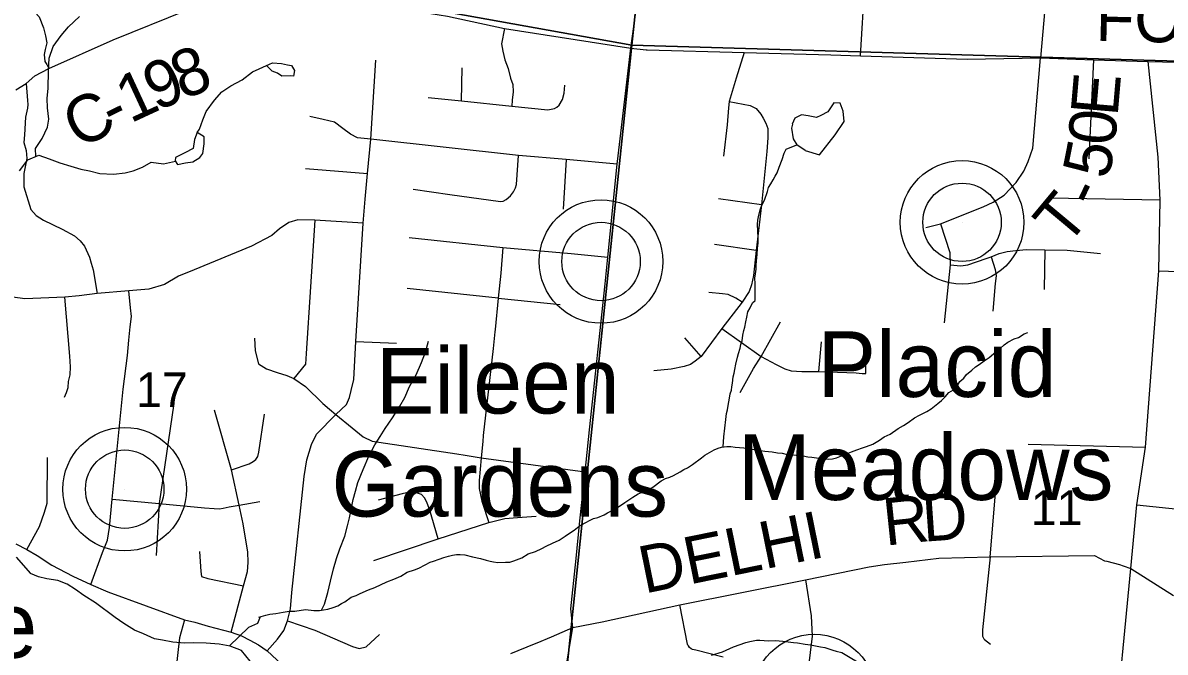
# Model space of a CAD drawing. Extents: x 0 to 34, y 0 to 22.
# Drawn here: x 6.917 to 8.292, y 15.497 to 16.255 of the extents above; entities that cross this region are included whole.
import ezdxf

# ---------------------------------------------------------------- set-up
doc = ezdxf.new("R2010")
doc.units = 0
for name, color, linetype in [('GM_X_Corporation', 7, 'Continuous'), ('GM_X_County_Road', 7, 'Continuous'), ('GM_X_County_Road_Text', 7, 'Continuous'), ('GM_X_Minor_Lake', 7, 'Continuous'), ('GM_X_Minor_River', 7, 'Continuous'), ('GM_X_Section_Text', 7, 'Continuous'), ('GM_X_Township_Road', 7, 'Continuous'), ('GM_X_Township_Road_Text', 7, 'Continuous'), ('GM_X_Unincorporated', 7, 'Continuous'), ('GM_X_Unincorporated_Location', 7, 'Continuous'), ('GM_X_Unincorporated_Text', 7, 'Continuous')]:
    doc.layers.add(name, color=color, linetype=linetype)

msp = doc.modelspace()

# ---------------------------------------------------------------- linework, layer by layer
at = {"layer": 'GM_X_Corporation'}
for points in [[(7.7575, 17.2431), (7.6501, 16.2281), (6.6267, 16.412), (6.7271, 17.3517)], [(7.7575, 17.2431), (8.7485, 17.1931), (8.6363, 16.199), (7.6501, 16.2281)], [(7.6501, 16.2281), (7.5438, 15.2065), (6.5194, 15.3963), (6.6267, 16.412)], [(8.6363, 16.199), (8.5356, 15.1763), (7.5438, 15.2065), (7.6501, 16.2281)]]:
    msp.add_lwpolyline(points, close=True, dxfattribs=at)
at = {"layer": 'GM_X_County_Road'}
for p, q in [((8.1491, 16.294), (8.1419, 16.2128)), ((7.5696, 15.4719), (7.579, 15.5268))]:
    msp.add_line(p, q, dxfattribs=at)
for points in [[(7.5825, 15.6055), (7.5876, 15.6552), (7.5938, 15.7142), (7.5992, 15.7646), (7.6179, 15.9406), (7.6211, 15.9725), (7.6324, 16.0848), (7.6334, 16.0947), (7.6488, 16.2243), (7.6616, 16.3174), (7.6639, 16.369), (7.6701, 16.4334), (7.6877, 16.6246), (7.6932, 16.6628)], [(6.9083, 16.174), (6.921, 16.1818), (6.9314, 16.1911), (6.9481, 16.2), (7.0257, 16.2344), (7.1152, 16.2704), (7.1761, 16.2963), (7.1774, 16.2968), (7.1787, 16.2968), (7.1812, 16.2964), (7.1889, 16.2949), (7.2573, 16.2866), (7.3578, 16.2742), (7.4283, 16.2628), (7.4967, 16.2481), (7.6488, 16.2243), (7.6674, 16.2224), (7.6684, 16.2224)], [(7.6684, 16.2224), (7.7851, 16.2192), (7.8897, 16.2164), (7.9253, 16.2153), (8.0538, 16.2113), (8.1419, 16.2128)], [(8.1419, 16.2128), (8.2056, 16.2102), (8.2716, 16.2083)], [(8.2507, 15.5975), (8.258, 15.6744), (8.2685, 15.744), (8.2845, 15.9563), (8.2862, 16.0414), (8.2836, 16.093), (8.2716, 16.2083)], [(8.2716, 16.2083), (8.427, 16.2047), (8.4709, 16.2033), (8.4984, 16.2029), (8.639, 16.2005)], [(8.2845, 15.9563), (8.4847, 15.9494), (8.6082, 15.9452), (8.7294, 15.9293), (8.7612, 15.9252)], [(8.258, 15.6744), (8.3155, 15.6683), (8.37, 15.6624), (8.4552, 15.6596), (8.5777, 15.6456), (8.693, 15.6342), (8.8525, 15.6133), (8.88, 15.6103), (8.9, 15.6093)], [(6.9083, 15.6272), (6.9219, 15.6204), (6.934, 15.6132), (6.9518, 15.6015), (6.9771, 15.5884), (6.9986, 15.5785), (7.0192, 15.5696), (7.1116, 15.536), (7.1241, 15.5332), (7.1402, 15.5282), (7.1676, 15.5211), (7.1803, 15.5165), (7.1902, 15.5115), (7.2006, 15.5058), (7.2112, 15.4987), (7.2347, 15.4766)], [(7.536, 15.5083), (7.5532, 15.5155), (7.579, 15.5268), (7.6143, 15.5334), (7.7079, 15.5539), (7.8591, 15.5842), (7.9358, 15.5995), (7.9541, 15.6024), (7.98, 15.6051), (8.0195, 15.6103), (8.0814, 15.6119), (8.2071, 15.6132), (8.219, 15.6071), (8.2217, 15.6066), (8.2369, 15.6023), (8.2415, 15.6007)], [(7.5775, 15.5567), (7.5818, 15.5986), (7.5825, 15.6055)], [(8.2129, 15.2407), (8.2301, 15.3849), (8.2507, 15.5975)], [(8.2415, 15.6007), (8.2507, 15.5975), (8.302, 15.5653)], [(7.579, 15.5268), (7.5767, 15.5489), (7.5775, 15.5567)], [(7.7598, 15.4908), (7.7271, 15.4992), (7.723, 15.5001), (7.7213, 15.5011), (7.7196, 15.5025), (7.7182, 15.5044), (7.7175, 15.5055), (7.7171, 15.5067), (7.7079, 15.5539)], [(7.5042, 15.4951), (7.5327, 15.5069), (7.536, 15.5083)]]:
    msp.add_lwpolyline(points, dxfattribs=at)
at = {"layer": 'GM_X_Minor_Lake'}
msp.add_line((7.1006, 16.0928), (7.1003, 16.0886), dxfattribs=at)
for points in [[(7.1933, 16.1959), (7.2137, 16.2049), (7.2175, 16.2067), (7.2281, 16.2057), (7.2357, 16.2043), (7.2402, 16.2034), (7.2438, 16.1976), (7.2429, 16.1908), (7.2395, 16.1909), (7.2285, 16.1908), (7.2236, 16.1944), (7.2169, 16.1968), (7.2132, 16.2007)], [(7.2132, 16.2007), (7.2102, 16.2034)], [(7.8587, 16.1012), (7.8761, 16.096), (7.8949, 16.1199), (7.9055, 16.1359), (7.9043, 16.1485), (7.9008, 16.1581), (7.8932, 16.1586), (7.8861, 16.1478), (7.8776, 16.1434), (7.8723, 16.1409), (7.8621, 16.1427), (7.8541, 16.144), (7.8461, 16.14), (7.8432, 16.1329)], [(7.8433, 16.133), (7.8424, 16.128), (7.8443, 16.115), (7.8487, 16.1081)], [(7.1003, 16.0886), (7.103, 16.0841), (7.1126, 16.0861), (7.1217, 16.0874), (7.1298, 16.0925), (7.1334, 16.0977), (7.1352, 16.109), (7.135, 16.1174), (7.1268, 16.1229), (7.1236, 16.1143), (7.1218, 16.1037), (7.1121, 16.0982), (7.1048, 16.0946)], [(7.8587, 16.1012), (7.8487, 16.1081)], [(7.1048, 16.0946), (7.1006, 16.0928)]]:
    msp.add_lwpolyline(points, dxfattribs=at)
at = {"layer": 'GM_X_Minor_River'}
for points in [[(6.9324, 16.0937), (6.9322, 16.1037), (6.94, 16.1157), (6.9465, 16.1292), (6.9482, 16.139), (6.9467, 16.1527), (6.9462, 16.1637), (6.9473, 16.1762), (6.9478, 16.1967), (6.9486, 16.2123), (6.9535, 16.2262), (6.9629, 16.2397), (6.9719, 16.2501), (6.9852, 16.2627)], [(7.1267, 16.1227), (7.1296, 16.127), (7.1337, 16.1379), (7.1374, 16.1481), (7.1476, 16.1618), (7.1566, 16.1719), (7.1674, 16.1792), (7.1809, 16.1864), (7.1933, 16.1959)], [(7.7986, 15.9203), (7.7984, 15.9411), (7.7982, 15.9472), (7.7987, 15.9525), (7.7996, 15.9582), (7.7997, 15.9631), (7.8002, 15.9677), (7.8008, 15.9757), (7.8014, 15.9829), (7.802, 15.9894), (7.8021, 15.9958), (7.8016, 16.0042), (7.8014, 16.0118), (7.8016, 16.0172), (7.8024, 16.0213), (7.8037, 16.0266), (7.805, 16.0308), (7.8066, 16.0353), (7.8098, 16.0413), (7.8132, 16.0519), (7.8144, 16.0564), (7.8172, 16.0609), (7.82, 16.0658), (7.8224, 16.0703), (7.8248, 16.0744), (7.8273, 16.0812), (7.8309, 16.0902), (7.8334, 16.0978), (7.8358, 16.1027), (7.8487, 16.1081)], [(6.9129, 16.0765), (6.9231, 16.0899), (6.9361, 16.0953), (6.9485, 16.0911), (6.9613, 16.0863), (6.9745, 16.0821), (6.9866, 16.0788), (6.9971, 16.0766), (7.0096, 16.0733), (7.0262, 16.0725), (7.04, 16.0744), (7.0499, 16.0765), (7.061, 16.0811), (7.0714, 16.0869), (7.0864, 16.0852), (7.1005, 16.0882)], [(7.7601, 15.7441), (7.7607, 15.7563), (7.7631, 15.7772), (7.7641, 15.7844), (7.765, 15.7889), (7.7659, 15.7938), (7.7676, 15.8029), (7.7685, 15.8079), (7.7698, 15.8124), (7.7703, 15.8166), (7.7711, 15.8207), (7.7721, 15.8287), (7.773, 15.8329), (7.7739, 15.8374), (7.7752, 15.8438), (7.7773, 15.8522), (7.7786, 15.8567), (7.7803, 15.8631), (7.7812, 15.8673), (7.7828, 15.8718), (7.7837, 15.8787), (7.785, 15.8843), (7.7859, 15.8885), (7.7872, 15.8949), (7.7885, 15.9002), (7.7898, 15.9067), (7.7926, 15.9115), (7.7954, 15.9176), (7.7986, 15.9203)], [(7.2763, 15.5474), (7.2799, 15.5546), (7.2841, 15.5686), (7.2874, 15.5826), (7.2908, 15.5973), (7.2945, 15.6098), (7.2985, 15.6215), (7.3045, 15.6365), (7.3078, 15.649), (7.3103, 15.6588), (7.3146, 15.6808), (7.3175, 15.691), (7.32, 15.7012), (7.3264, 15.717), (7.3336, 15.7328), (7.3407, 15.7467), (7.347, 15.7565), (7.3529, 15.7662), (7.3619, 15.7793), (7.3706, 15.7932), (7.3769, 15.8037), (7.3825, 15.8169), (7.3904, 15.8311), (7.3968, 15.8458), (7.4016, 15.8583), (7.4053, 15.8715)], [(7.8619, 15.7321), (7.8668, 15.7316), (7.8725, 15.7311), (7.8775, 15.7305), (7.8828, 15.7296), (7.8873, 15.7295), (7.8915, 15.7298), (7.8965, 15.7311), (7.9023, 15.7333), (7.9065, 15.7351), (7.9146, 15.7383), (7.9207, 15.7404), (7.9276, 15.7432), (7.9326, 15.7446), (7.9403, 15.7474), (7.948, 15.7522), (7.9538, 15.7562), (7.9608, 15.7594), (7.9708, 15.7664), (7.977, 15.7697), (7.9825, 15.7737), (7.9902, 15.7792), (7.9964, 15.7824), (8.0052, 15.7868), (8.0103, 15.7901), (8.0184, 15.7963), (8.0227, 15.8), (8.027, 15.8044), (8.0317, 15.8096), (8.0371, 15.8129), (8.0426, 15.8189), (8.045, 15.823), (8.0497, 15.827), (8.0529, 15.8315), (8.0591, 15.8367), (8.0638, 15.8407), (8.068, 15.8433), (8.0742, 15.8477), (8.08, 15.8517), (8.0882, 15.8587), (8.0933, 15.8628), (8.0983, 15.8672), (8.1026, 15.8701), (8.1103, 15.8741), (8.1153, 15.8759), (8.1222, 15.8802), (8.1268, 15.882)], [(7.2011, 15.5392), (7.2095, 15.5416), (7.2141, 15.5426), (7.2213, 15.5436), (7.2301, 15.5449), (7.2374, 15.5462), (7.2442, 15.5464), (7.2572, 15.5483), (7.2671, 15.5472), (7.2739, 15.5471), (7.2789, 15.5477), (7.2842, 15.5487), (7.2904, 15.5508), (7.2961, 15.5529), (7.3004, 15.5555), (7.3046, 15.5576), (7.312, 15.5631), (7.3181, 15.5652), (7.3231, 15.5674), (7.3332, 15.5721), (7.3405, 15.5749), (7.3551, 15.5817), (7.3636, 15.5849), (7.372, 15.5885), (7.3797, 15.5932), (7.3882, 15.596), (7.3936, 15.5982), (7.4013, 15.6022), (7.4071, 15.6054), (7.4113, 15.6064), (7.4182, 15.6089), (7.4236, 15.6111), (7.4293, 15.6124), (7.4343, 15.6138), (7.4389, 15.6144), (7.4435, 15.6147), (7.4491, 15.6141), (7.4582, 15.6116), (7.4677, 15.6098), (7.4745, 15.6077), (7.4794, 15.6064), (7.4835, 15.6056), (7.4888, 15.6047), (7.498, 15.6052), (7.5033, 15.6054), (7.5079, 15.6068), (7.5175, 15.6107), (7.5252, 15.6154), (7.5341, 15.6182), (7.5418, 15.6218), (7.5468, 15.6244), (7.5545, 15.628), (7.5626, 15.6319), (7.5699, 15.6367), (7.575, 15.6403), (7.5804, 15.644), (7.5866, 15.6488), (7.5939, 15.6528), (7.5997, 15.656), (7.604, 15.6578), (7.6089, 15.6592), (7.6166, 15.6624), (7.6209, 15.6646), (7.6278, 15.6682), (7.6329, 15.6711), (7.6414, 15.677), (7.6464, 15.6802), (7.6511, 15.6835), (7.6576, 15.6875), (7.6696, 15.6925), (7.6754, 15.6958), (7.6854, 15.7031), (7.6905, 15.7061), (7.6958, 15.7078), (7.7001, 15.7096), (7.7082, 15.7139), (7.7128, 15.7169), (7.7171, 15.719), (7.7229, 15.723), (7.7337, 15.7311), (7.738, 15.7341), (7.7434, 15.7373), (7.7492, 15.7406), (7.7538, 15.7424), (7.758, 15.7438), (7.7645, 15.7447), (7.7691, 15.7446), (7.7744, 15.7437), (7.7797, 15.7436), (7.785, 15.743), (7.7896, 15.7421), (7.7998, 15.7407), (7.81, 15.7389), (7.8191, 15.7383), (7.8255, 15.7369), (7.8309, 15.7364), (7.8369, 15.7351), (7.8411, 15.735), (7.8513, 15.7339), (7.8562, 15.7334), (7.8619, 15.7321)], [(6.9089, 15.6114), (6.926, 15.5915)], [(7.1905, 15.4862), (7.1802, 15.499), (7.1663, 15.5042), (7.1534, 15.5065), (7.1375, 15.5076), (7.1227, 15.508), (7.1117, 15.5079), (7.0973, 15.509), (7.0852, 15.5112), (7.0754, 15.513), (7.0623, 15.519), (7.0514, 15.5234), (7.0383, 15.5314), (7.0279, 15.5388), (7.0044, 15.5565), (6.9902, 15.5652), (6.9805, 15.5723), (6.9701, 15.5786), (6.9592, 15.5831), (6.9456, 15.5853), (6.9357, 15.5875), (6.926, 15.5915)], [(7.2026, 15.5396), (7.1992, 15.5315), (7.1885, 15.5265), (7.1655, 15.5044)], [(7.7459, 15.4931), (7.759, 15.4973), (7.7724, 15.5034), (7.7874, 15.5087), (7.792, 15.5097), (7.8, 15.5114), (7.8042, 15.5113), (7.8145, 15.5106), (7.8228, 15.5108), (7.8316, 15.5102), (7.8448, 15.5086), (7.8494, 15.5081), (7.8588, 15.5067), (7.8649, 15.5058), (7.877, 15.5035), (7.8823, 15.5026), (7.8921, 15.4993)], [(7.8921, 15.4993), (7.8959, 15.4981), (7.9027, 15.4964), (7.915, 15.4892), (7.9195, 15.4864), (7.9233, 15.484), (7.9338, 15.4787), (7.9387, 15.4771), (7.947, 15.4749), (7.9575, 15.4712), (7.9673, 15.4675), (7.9775, 15.4638), (7.9805, 15.463), (7.9854, 15.4621), (7.9884, 15.4616)]]:
    msp.add_lwpolyline(points, dxfattribs=at)
at = {"layer": 'GM_X_Township_Road'}
for p, q in [((7.4449, 16.1609), (7.4459, 16.2006)), ((8.2056, 16.2102), (8.2, 16.0909)), ((7.5711, 16.0902), (7.5672, 16.0304)), ((7.2571, 16.0796), (7.332, 16.0735)), ((7.8061, 16.0358), (7.7542, 16.0428)), ((8.2862, 16.0414), (8.1535, 16.0438)), ((7.4948, 15.9843), (7.4924, 15.9533)), ((7.7995, 15.9807), (7.7497, 15.9879)), ((8.1472, 15.9815), (8.1465, 15.9338)), ((7.4892, 15.9232), (7.3797, 15.935)), ((7.4892, 15.9232), (7.5636, 15.9158)), ((7.8058, 15.853), (7.829, 15.8948)), ((7.3178, 15.8712), (7.3666, 15.8689)), ((7.7336, 15.8531), (7.7137, 15.8754)), ((7.8752, 15.8351), (7.8782, 15.8707)), ((8.1273, 15.7474), (8.2685, 15.744)), ((8.0814, 15.6119), (8.0889, 15.7028))]:
    msp.add_line(p, q, dxfattribs=at)
for points in [[(7.9253, 16.2153), (7.9303, 16.3013), (7.9386, 16.4436)], [(6.8522, 16.2841), (6.8581, 16.2826), (6.8632, 16.2815), (6.8724, 16.2806), (6.8921, 16.2771), (6.9079, 16.2745), (6.9195, 16.2723), (6.9257, 16.2703), (6.9318, 16.2672), (6.9367, 16.2622), (6.9419, 16.249), (6.9443, 16.2391), (6.9459, 16.2306), (6.9439, 16.2229), (6.9426, 16.2166), (6.9432, 16.2082), (6.9456, 16.2045), (6.9481, 16.2)], [(7.4967, 16.2481), (7.4931, 16.2294), (7.4948, 16.2207), (7.4973, 16.2105), (7.5011, 16.1999), (7.5041, 16.1883), (7.5069, 16.1807), (7.5071, 16.1718), (7.5061, 16.1618), (7.5055, 16.1547)], [(7.7851, 16.2192), (7.7755, 16.1881), (7.7672, 16.1603), (7.7665, 16.1526), (7.7646, 16.132), (7.7604, 16.0942)], [(8.0038, 16.0084), (8.0217, 16.0129), (8.0731, 16.0334), (8.0848, 16.0388), (8.0981, 16.0474), (8.1127, 16.0626), (8.1219, 16.0763), (8.1273, 16.088), (8.1328, 16.1038), (8.1419, 16.2128)], [(7.3274, 16.0234), (7.3291, 16.0425), (7.332, 16.0735), (7.336, 16.1148), (7.3417, 16.2098)], [(6.921, 16.1818), (6.9224, 16.1615), (6.923, 16.1567), (6.9226, 16.152), (6.9201, 16.1411), (6.9191, 16.1198), (6.918, 16.1106), (6.9209, 16.1013), (6.9216, 16.0913), (6.9182, 16.0736), (6.918, 16.0572), (6.9266, 16.0301), (6.933, 16.023), (6.9419, 16.0173), (6.9643, 16.0063), (6.9789, 15.9985), (6.986, 15.9924), (6.991, 15.986), (6.997, 15.9728), (6.9992, 15.9655)], [(7.4048, 16.1648), (7.4449, 16.1609), (7.5055, 16.1547), (7.5487, 16.1501), (7.5529, 16.1508), (7.5568, 16.1518), (7.5596, 16.1533), (7.5625, 16.1556), (7.5666, 16.1625), (7.5685, 16.1702), (7.5692, 16.1799)], [(7.7672, 16.1603), (7.7925, 16.1553), (7.7996, 16.1517), (7.8051, 16.1447), (7.8081, 16.1402), (7.8115, 16.134), (7.8136, 16.1277), (7.8136, 16.1165), (7.8127, 16.1001), (7.8061, 16.0358), (7.7995, 15.9807), (7.7964, 15.9507), (7.7939, 15.9393), (7.7914, 15.9313), (7.783, 15.9183), (7.7585, 15.8869), (7.7336, 15.8531), (7.7264, 15.8475), (7.7205, 15.8433), (7.713, 15.8408), (7.6973, 15.8377), (7.6763, 15.8357)], [(7.6324, 16.0848), (7.5711, 16.0902), (7.5135, 16.0952), (7.336, 16.1148), (7.3198, 16.1162), (7.3114, 16.1207), (7.3023, 16.1276), (7.292, 16.1351), (7.2783, 16.1385), (7.2623, 16.1419)], [(7.3867, 16.0545), (7.4308, 16.048), (7.4921, 16.0397), (7.495, 16.0399), (7.4989, 16.0421), (7.504, 16.0466), (7.5074, 16.0514), (7.5099, 16.0561), (7.5111, 16.06), (7.5135, 16.0952)], [(7.2112, 15.4987), (7.2233, 15.5126), (7.2312, 15.5229), (7.2354, 15.5346), (7.239, 15.5492), (7.2408, 15.5688), (7.2555, 15.7084), (7.2587, 15.7284), (7.2644, 15.7472), (7.2705, 15.7593), (7.2936, 15.7832), (7.3064, 15.7952), (7.31, 15.8035), (7.3121, 15.8122), (7.3152, 15.8254), (7.3178, 15.8712), (7.3264, 16.0134), (7.3274, 16.0234)], [(7.3264, 16.0134), (7.2685, 16.0173), (7.2479, 16.0177), (7.2372, 16.0145), (7.2258, 16.0066), (7.2166, 15.9988), (7.192, 15.9857), (7.123, 15.9575), (7.1043, 15.9497), (7.0876, 15.9397), (7.0685, 15.9342), (7.0445, 15.9319), (7.0063, 15.9287), (6.9846, 15.9262), (6.9675, 15.9243), (6.9484, 15.9237), (6.9193, 15.9223), (6.8495, 15.9319)], [(7.2685, 16.0173), (7.258, 15.8568), (7.257, 15.8437), (7.2431, 15.8266)], [(8.0217, 16.0129), (8.0329, 15.9783), (8.0333, 15.9635), (8.0261, 15.8936)], [(7.382, 15.9963), (7.4948, 15.9843), (7.5769, 15.9771), (7.6211, 15.9725)], [(8.0333, 15.9635), (8.0462, 15.9622), (8.0545, 15.9633), (8.0764, 15.9709), (8.0824, 15.9731), (8.092, 15.977), (8.1017, 15.9794), (8.1121, 15.9806), (8.125, 15.9819), (8.1472, 15.9815), (8.1742, 15.9811), (8.2143, 15.9772)], [(6.9992, 15.9655), (7.0016, 15.9572), (7.0063, 15.9287)], [(8.0824, 15.9731), (8.0873, 15.9578), (8.0887, 15.9501), (8.0873, 15.9411), (8.0845, 15.9078)], [(7.4924, 15.9533), (7.4892, 15.9232), (7.4855, 15.8857), (7.4852, 15.8827)], [(6.9669, 15.8042), (6.9694, 15.8095), (6.9716, 15.8156), (6.9719, 15.8227), (6.9737, 15.8309), (6.9744, 15.8405), (6.9734, 15.8536), (6.9675, 15.9243)], [(6.9986, 15.5785), (7.0129, 15.6168), (7.0189, 15.6318), (7.0214, 15.6471), (7.0246, 15.6812), (7.0321, 15.7574), (7.0378, 15.8136), (7.0427, 15.8542), (7.0447, 15.8728), (7.0463, 15.8889), (7.0477, 15.9011), (7.0467, 15.9115), (7.0445, 15.9319)], [(7.783, 15.9183), (7.7753, 15.9234), (7.7659, 15.9275), (7.7593, 15.9286), (7.7426, 15.9302)], [(7.4852, 15.8827), (7.4832, 15.8627), (7.4711, 15.7578), (7.4705, 15.7508)], [(7.7585, 15.8869), (7.8058, 15.853), (7.8238, 15.8434), (7.8343, 15.838), (7.842, 15.8357), (7.8545, 15.8351), (7.8752, 15.8351), (7.9199, 15.8333), (7.9273, 15.8324), (7.9317, 15.8325), (7.9316, 15.8375), (7.9321, 15.8617), (7.9339, 15.8704)], [(7.1956, 15.8749), (7.1964, 15.8597), (7.2006, 15.8441), (7.2103, 15.838), (7.2232, 15.8337), (7.2345, 15.8301), (7.2431, 15.8266), (7.257, 15.817), (7.278, 15.7963), (7.2862, 15.7894)], [(7.7803, 15.8095), (7.7963, 15.8384), (7.8058, 15.853)], [(7.0987, 15.7963), (7.0812, 15.6759), (7.0773, 15.6135)], [(7.1676, 15.5211), (7.1824, 15.5769), (7.1872, 15.5939), (7.1883, 15.6047), (7.1877, 15.6179), (7.1851, 15.6344), (7.1822, 15.6513), (7.1773, 15.6741), (7.168, 15.7166), (7.1477, 15.7885)], [(7.2862, 15.7894), (7.2936, 15.7832), (7.3132, 15.7672), (7.3267, 15.7561), (7.3374, 15.7511), (7.4395, 15.7356), (7.4493, 15.734)], [(7.168, 15.7166), (7.1894, 15.7236), (7.1943, 15.7264), (7.1974, 15.7289), (7.1996, 15.7325), (7.201, 15.7376), (7.208, 15.7835)], [(7.4705, 15.7508), (7.4687, 15.7309), (7.4663, 15.7036), (7.4664, 15.6941), (7.4694, 15.6789), (7.478, 15.6531)], [(6.9219, 15.6204), (6.9369, 15.6484), (6.943, 15.6657), (6.946, 15.6763), (6.9464, 15.7314)], [(7.4493, 15.734), (7.4687, 15.7309), (7.5938, 15.7142)], [(7.417, 15.6333), (7.4066, 15.6691), (7.4027, 15.6784), (7.4004, 15.6826), (7.3969, 15.6869), (7.3919, 15.6886), (7.384, 15.6902), (7.3735, 15.6875), (7.3445, 15.6799)], [(7.0246, 15.6812), (7.0812, 15.6759), (7.1354, 15.6707), (7.1472, 15.6698), (7.1536, 15.6697), (7.158, 15.6705), (7.1653, 15.6721), (7.1773, 15.6741), (7.2023, 15.6782)], [(7.3395, 15.6074), (7.417, 15.6333), (7.478, 15.6531), (7.4971, 15.6577), (7.5122, 15.6589), (7.535, 15.6608)], [(7.1297, 15.6181), (7.1311, 15.5942), (7.132, 15.588), (7.1397, 15.5855), (7.1824, 15.5769)], [(8.0814, 15.6119), (8.072, 15.5239), (8.072, 15.5182), (8.0723, 15.5161), (8.0729, 15.5145), (8.0737, 15.5131), (8.0747, 15.5121), (8.0817, 15.5066)], [(7.8591, 15.5842), (7.866, 15.5407), (7.8669, 15.516), (7.8621, 15.4767), (7.8573, 15.4611), (7.8553, 15.4561)], [(7.1116, 15.536), (7.1054, 15.5142), (7.0972, 15.4398), (7.1057, 15.417), (7.1114, 15.4092), (7.116, 15.4029), (7.1269, 15.396), (7.137, 15.39), (7.1733, 15.3814), (7.2043, 15.3763)], [(7.2354, 15.5346), (7.2685, 15.5234), (7.3139, 15.5038), (7.3217, 15.5015), (7.3301, 15.5033), (7.3463, 15.5181)]]:
    msp.add_lwpolyline(points, dxfattribs=at)
at = {"layer": 'GM_X_Unincorporated'}
for centre, radius in [((8.0475, 16.0146), 0.0744), ((8.0475, 16.0146), 0.0472), ((7.6129, 15.9674), 0.0744), ((7.6129, 15.9674), 0.0472), ((7.0395, 15.6932), 0.0744), ((7.0395, 15.6932), 0.0472), ((7.8697, 15.444), 0.0744)]:
    msp.add_circle(centre, radius, dxfattribs=at)
at = {"layer": 'GM_X_Unincorporated_Location'}
for p, q in [((8.0475, 16.0146), (8.0475, 16.0146)), ((7.6129, 15.9674), (7.6129, 15.9674)), ((7.0395, 15.6932), (7.0395, 15.6932))]:
    msp.add_line(p, q, dxfattribs=at)

# ---------------------------------------------------------------- texts
at = {"layer": 'GM_X_County_Road_Text'}
for s, height, rotation, p in [('FOLEY', 0.05682, 358.5154, (8.2079, 16.2334)), ('9', 0.0568, 23.2637, (7.0776, 16.148)), ('8', 0.0568, 22.1995, (7.1095, 16.1617)), ('1', 0.0568, 24.8624, (7.0462, 16.1334)), ('C', 0.0568, 26.9032, (6.9841, 16.1022)), ('-', 0.0568, 26.1732, (7.0256, 16.1233)), ('R', 0.0568, 6, (7.9553, 15.6251)), ('D', 0.0568, 4.0176, (8.0012, 15.6299)), ('DELHI', 0.05682, 11.4874, (7.6651, 15.5673))]:
    msp.add_text(s, height=height, rotation=rotation, dxfattribs=at).set_placement(p)
at = {"layer": 'GM_X_Section_Text'}
for s, p in [('17', (7.0531, 15.792)), ('11', (8.1302, 15.6499))]:
    msp.add_text(s, height=0.04186, rotation=0, dxfattribs=at).set_placement(p)
at = {"layer": 'GM_X_Township_Road_Text'}
for s, rotation, p in [('E', 85.0858, (8.2347, 16.1413)), ('0', 84.6987, (8.2314, 16.106)), ('5', 78.8571, (8.2238, 16.0654)), ('T', 50.1426, (8.1733, 15.984)), ('-', 64.6372, (8.209, 16.0298))]:
    msp.add_text(s, height=0.0568, rotation=rotation, dxfattribs=at).set_placement(p)
at = {"layer": 'GM_X_Unincorporated_Text'}
for s, p in [('Placid', (7.8735, 15.8043)), ('Eileen', (7.3418, 15.7843)), ('Meadows', (7.7777, 15.6802)), ('Gardens', (7.2885, 15.6602)), ('Sunaire', (6.5702, 15.4902))]:
    msp.add_text(s, height=0.07898, rotation=0, dxfattribs=at).set_placement(p)

doc.saveas('drawing.dxf')
